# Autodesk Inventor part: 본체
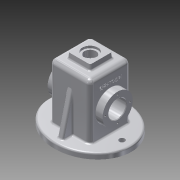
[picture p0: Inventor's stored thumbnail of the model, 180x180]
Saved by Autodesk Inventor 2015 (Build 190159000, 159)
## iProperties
Created: 2017-07
Part Number: 본체
Material: 알루미늄 6061
Document SubType Name: Modeling
Designer: Admin
Density: 2.7 g/cm^3
Appearance: 알루미늄 - 평지
Mass: 893.274 g
Surface Area: 987.904 cm^2
Volume: 330.842 cm^3
Author: Admin
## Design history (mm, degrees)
sketch "스케치1"
  geometry: L1 (-75, 65)-(75, 65); L2 (75, 65)-(75, -65); L3 (75, -65)-(-75, -65); L4 (-75, -65)-(-75, 65); L5 (-75, 65)-(75, -65); L6 (75, 65)-(-75, -65); 1 further point
  constraints: 12 end point, 2 midpoint, 2 parallel, 1 horizontal, 1 perpendicular
  dimensions: "d0" = 150 distance of L2.end L3.end; "d1" = 130 distance of L1.end L2.end
extrude "돌출1" new body sketch "스케치1" distance "d2" = 10; taper "d3" = 0 deg
sketch "스케치2" dims "d7" = 65, "d123" = 75
  geometry: L1 (75, 65)-(-75, 65) reference; L2 (-75, 65)-(-75, -65) reference; L3 (-75, -65)-(75, -65) reference; L4 (75, -65)-(75, 65) reference; L5 (-75, 65)-(-75, -65) reference; L6 (-75, -65)-(-75, 65) reference; 10 further points; 1 other entity
  constraints: 8 midpoint, 4 horizontal alignment, 3 coincident, 1 horizontal, 1 vertical alignment, 2 other
extrude "돌출2" cut sketch "스케치2" distance "d8" = 10; taper "d9" = 0 deg
sketch "스케치3"
  geometry: L1 (-75, 0)-(75, 0) reference; L2 (37, 110)-(-37, 110); L3 (-37, 110)-(-37, 10); L4 (37, 10)-(37, 110); L5 (75, 10)-(-75, 10) reference; 3 further points
  constraints: 6 end point, 2 midpoint, 2 point on line, 1 horizontal, 1 parallel, 1 perpendicular, 1 vertical alignment
  dimensions: "d10" = 74 distance of L2.start L2.end; "d11" = 110 distance between parallel lines of L1 L2
extrude "돌출3" join sketch "스케치3" stored distance "d13" = 74; taper "d14" = 0 deg
sketch "스케치4"
  geometry: L1 (-32, 0)-(-32, 105); L2 (32, 105)-(32, 0); L3 (-32, 0)-(32, 0); L4 (-37, 110)-(37, 110) reference; L5 (-37, 10)-(-37, 110) reference; L6 (37, 110)-(37, 10) reference; L7 (-32, 105)-(32, 105); 5 further points
  constraints: 8 end point, 4 midpoint, 2 vertical alignment, 1 horizontal, 1 horizontal alignment
  dimensions: "d16" = 105 distance of L1.start L1.end; "d17" = 105 distance of L2.start L2.end; "d18" = 64 distance of L1.start L2.end; "d19" = 64 distance of L1.end L2.start; "d125" = 5 distance between parallel lines of L7 L4
extrude "돌출4" cut sketch "스케치4" stored distance "d20" = 64; taper "d21" = 0 deg
node "작업 평면1"
sketch "스케치5"
  geometry: L1 (20, -20)-(-20, -20); L2 (-20, -20)-(-20, 20); L3 (-20, 20)-(20, 20); L4 (20, 20)-(20, -20); L5 (20, -20)-(-20, 20); L6 (-20, -20)-(20, 20); 1 further point
  constraints: 12 end point, 2 midpoint, 2 parallel, 1 horizontal, 1 perpendicular
  dimensions: "d23" = 40 distance of L2.end L3.end; "d24" = 40 distance of L1.end L2.end
extrude "돌출5" join sketch "스케치5" stored distance "d25" = 64; taper "d26" = 5 deg
sketch "스케치6"
  geometry: 2 further points
  constraints: 1 coincident
hole "구멍1" sketch "스케치6" at (0, 0) diameter "d27" = 21; stored, may be unused: countersink angle "d31" = 90 deg, drill point angle "d33" = 0 deg; dims "d28" = 6, "d29" = 28, "d30" = 4, "d32" = 8
sketch "스케치7"
  geometry: L1 (-110, 102)-(-110, -28) reference; C1 r 27.5 at (-55, 37); 2 further points
  constraints: 1 centre point, 1 horizontal alignment, 1 midpoint
  dimensions: "d34" = 55 diameter of C1; "d35" = 55 distance from line of L1 C1.centre
extrude "돌출6" join sketch "스케치7" distance "d36" = 13; taper "d37" = 0 deg
sketch "스케치8"
  geometry: L1 (10, -28)-(10, 102) reference; C1 r 27.5 at (-45, 37); 2 further points
  constraints: 1 centre point, 1 horizontal alignment, 1 midpoint
  dimensions: "d38" = 55 diameter of C1; "d39" = 55 distance from line of L1 C1.centre
extrude "돌출7" join sketch "스케치8" distance "d40" = 13; taper "d41" = 0 deg
sketch "스케치9"
  geometry: L1 (55, -65)-(55, 65) reference; L2 (45, 37)-(45, -37) reference; C1 r 27.5 at (0, 0); 4 further points
  constraints: 2 midpoint, 1 centre point, 1 horizontal alignment, 1 vertical alignment
  dimensions: "d97" = 55 diameter of C1; "d98" = 55 distance from line of L1 C1.centre; "d99" = 22.5 distance of point (0, 22.5) C1.centre
hole "구멍3" sketch "스케치9" at (0, 22.5) diameter "d52" = 3.242; stored, may be unused: countersink angle "d56" = 90 deg, drill point angle "d58" = 118 deg; dims "d53" = 8, "d54" = 28, "d55" = 4, "d57" = 10
sketch "스케치10"
  geometry: L1 (-55, 65)-(-55, -65) reference; C1 r 27.5 at (0, 0); 3 further points
  constraints: 2 horizontal alignment, 1 centre point, 1 midpoint
  dimensions: "d100" = 55 diameter of C1; "d101" = 55 distance from line of L1 C1.centre; "d102" = 22.5 distance of C1.centre point (22.5, 0)
hole "구멍4" sketch "스케치10" at (22.5, 0) diameter "d63" = 3.242; stored, may be unused: countersink angle "d67" = 90 deg, drill point angle "d69" = 118 deg; dims "d64" = 8, "d65" = 28, "d66" = 4, "d68" = 10
sketch "스케치11"
  geometry: C1 r 27.5 at (50, 32) reference; 1 further point
extrude "돌출8" join sketch "스케치11" distance "d73" = 7; taper "d74" = -45 deg
sketch "스케치12"
  geometry: C1 r 27.5 at (55, 32) reference; 1 further point
extrude "돌출9" join sketch "스케치12" distance "d75" = 7; taper "d76" = -45 deg
hole "구멍5" diameter "d79" = 32; stored, may be unused: countersink angle "d83" = 90 deg, drill point angle "d85" = 0 deg; dims "d77" = 10, "d78" = 10, "d80" = 8, "d81" = 28, "d82" = 4, "d84" = 10
sketch "스케치13"
  geometry: L1 (37, 110)-(37, 10) reference; L2 (-37, 10)-(-37, 110) reference; L3 (-55, 10)-(-37, 82.194); L4 (55, 10)-(37, 82.194); L5 (55, 10)-(37, 10); L6 (-55, 10)-(-37, 10); 3 further points
  constraints: 8 end point, 2 point on line, 1 horizontal
  dimensions: "d86" = 10 distance of point (-65, 10) L3.start; "d88" = 10 distance of point (65, 10) L4.start; "d90" = 110 distance of L4.start L3.start; "d126" = 72.19406 vertical distance of L4.start L4.end; "d127" = 72.19406 vertical distance of L3.start L3.end
extrude "돌출10" join sketch "스케치13" stored distance "d95" = 10; taper "d96" = 0 deg
sketch "스케치14"
  geometry: 3 further points
  constraints: 2 horizontal alignment
  dimensions: "d103" = 116 distance of point (58, 0) point (-58, 0); "d104" = 58 distance of point (0, 0) point (-58, 0)
hole "구멍6" sketch "스케치14" at (-58, 0), (58, 0) diameter "d105" = 10; stored, may be unused: countersink angle "d109" = 90 deg, drill point angle "d111" = 0 deg; dims "d106" = 8, "d107" = 28, "d108" = 4, "d110" = 10
fillet "모깎기1" dims "d112" = 8, "d113" = 3, "d114" = 0.5
fillet "모깎기2" dims "d115" = 3
chamfer "모따기1" distance "d116" = 1; stored, may be unused: second distance "d117" = 2, angle "d118" = 45 deg
fillet "모깎기3" dims "d124" = 3
sketch "스케치15"
  geometry: L1 (89, 66)-(0, 66) reference; L2 (-18, 9)-(-18, 49) reference; 2 further points
  constraints: 1 other
  dimensions: "d119" = 37 distance from line of L1 point (12, 29); "d120" = 30 distance from line of point (12, 29) L2
feature "엠보싱1" sketch "스케치15" dims "d0" = 150, "d1" = 130, "d121" = 0.5, "d122" = 0
node "솔리드1"
pattern_circular "원형 패턴1" dims angle "d60" = 360 deg
pattern_circular "원형 패턴2" dims angle "d71" = 360 deg
node "투영된 루프1"
